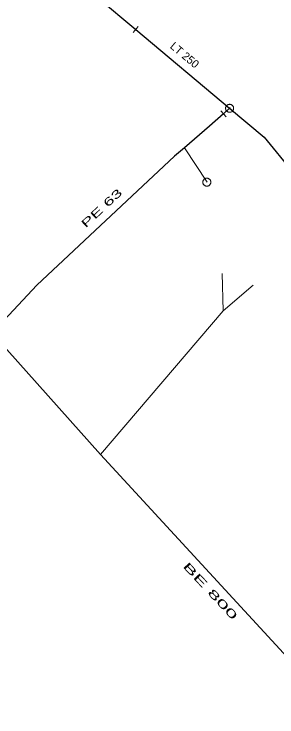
# Model space of a CAD drawing. Extents: x -807203 to -805207, y -993656 to -992505.
# Drawn here: x -805837.6 to -805804.7, y -993521.1 to -993433.3 of the extents above; entities that cross this region are included whole.
import ezdxf

# ---------------------------------------------------------------- set-up
doc = ezdxf.new("R2010")
doc.units = 0
doc.header["$LTSCALE"] = 0.4
for name, color, linetype, lineweight in [('1', 7, 'Continuous', 13), ('11', 7, 'Continuous', 13), ('13', 7, 'Continuous', 13), ('14', 7, 'Continuous', 25), ('17', 7, 'Continuous', 25), ('23', 7, 'Continuous', 13), ('34', 7, 'Continuous', 13), ('47', 7, 'Continuous', 13)]:
    doc.layers.add(name, color=color, linetype=linetype, lineweight=lineweight)

msp = doc.modelspace()

# ---------------------------------------------------------------- linework, layer by layer
at = {"layer": '11'}
msp.add_line((-805811.447, -993470.358), (-805811.581, -993465.673), dxfattribs=at)
msp.add_lwpolyline([(-805807.701, -993467.145), (-805811.447, -993470.358), (-805826.754, -993488.288)], dxfattribs=at)
at = {"layer": '13'}
msp.add_line((-805816.254, -993449.989), (-805813.444, -993454.292), dxfattribs=at)
at = {"layer": '14', "lineweight": 13}
msp.add_line((-805811.384, -993445.766), (-805810.637, -993445.063), dxfattribs=at)
at = {"layer": '14'}
msp.add_lwpolyline([(-805843.754, -993470.162), (-805838.469, -993475.18), (-805826.754, -993488.287), (-805799.036, -993518.404)], dxfattribs=at)
at = {"layer": '17'}
for p, q in [((-805830.275, -993428.564), (-805822.361, -993435.213)), ((-805822.361, -993435.213), (-805810.637, -993445.063))]:
    msp.add_line(p, q, dxfattribs=at)
for points in [[(-805810.637, -993445.063), (-805806.327, -993448.671), (-805795.712, -993461.664), (-805787.671, -993471.416), (-805755.36, -993508.868), (-805722.18, -993547.329), (-805706.16, -993565.899), (-805691.895, -993582.435), (-805667.369, -993617.68)], [(-805811.384, -993445.766), (-805813.146, -993447.293), (-805816.254, -993449.989), (-805817.509, -993451.022), (-805834.715, -993467.127), (-805848.12, -993481.456), (-805848.94, -993482.359), (-805854.633, -993489.281), (-805856.36, -993491.412), (-805860.274, -993496.243), (-805860.927, -993497.096), (-805863.272, -993500.095), (-805876.087, -993516.164)]]:
    msp.add_lwpolyline(points, dxfattribs=at)
at = {"layer": '23'}
for points in [[(-805813.197, -993454.701), (-805813.155, -993454.669), (-805813.116, -993454.633), (-805813.083, -993454.594), (-805813.053, -993454.551), (-805813.027, -993454.506), (-805813.007, -993454.457), (-805812.991, -993454.407), (-805812.981, -993454.357), (-805812.976, -993454.304), (-805812.977, -993454.252), (-805812.982, -993454.2), (-805812.995, -993454.148), (-805813.011, -993454.099), (-805813.033, -993454.052), (-805813.059, -993454.007), (-805813.092, -993453.964), (-805813.126, -993453.927), (-805813.167, -993453.891), (-805813.208, -993453.862), (-805813.253, -993453.835), (-805813.303, -993453.816), (-805813.353, -993453.8), (-805813.405, -993453.79), (-805813.456, -993453.784), (-805813.508, -993453.786), (-805813.561, -993453.792), (-805813.611, -993453.804), (-805813.661, -993453.821), (-805813.708, -993453.843), (-805813.753, -993453.869), (-805813.795, -993453.9), (-805813.834, -993453.936), (-805813.869, -993453.976), (-805813.899, -993454.018), (-805813.923, -993454.063), (-805813.944, -993454.112), (-805813.96, -993454.162), (-805813.97, -993454.214), (-805813.975, -993454.265)], [(-805813.167, -993453.891), (-805813.208, -993453.862), (-805813.253, -993453.835), (-805813.303, -993453.816), (-805813.353, -993453.8), (-805813.405, -993453.79), (-805813.456, -993453.784), (-805813.508, -993453.786), (-805813.561, -993453.792), (-805813.611, -993453.804), (-805813.661, -993453.821), (-805813.708, -993453.843), (-805813.753, -993453.869), (-805813.795, -993453.9), (-805813.834, -993453.936), (-805813.869, -993453.976), (-805813.899, -993454.018), (-805813.923, -993454.063), (-805813.944, -993454.112), (-805813.96, -993454.162), (-805813.97, -993454.214), (-805813.975, -993454.265), (-805813.974, -993454.317), (-805813.968, -993454.37), (-805813.957, -993454.42), (-805813.939, -993454.47), (-805813.917, -993454.517), (-805813.891, -993454.562), (-805813.859, -993454.603), (-805813.824, -993454.642), (-805813.784, -993454.678), (-805813.741, -993454.707), (-805813.696, -993454.733), (-805813.649, -993454.754), (-805813.598, -993454.768), (-805813.547, -993454.779), (-805813.495, -993454.784), (-805813.442, -993454.784), (-805813.39, -993454.777), (-805813.339, -993454.765)], [(-805813.975, -993454.265), (-805813.974, -993454.317), (-805813.968, -993454.37), (-805813.957, -993454.42), (-805813.939, -993454.47), (-805813.917, -993454.517), (-805813.891, -993454.562), (-805813.859, -993454.603), (-805813.824, -993454.642), (-805813.784, -993454.678), (-805813.741, -993454.707), (-805813.696, -993454.733), (-805813.649, -993454.754), (-805813.598, -993454.768), (-805813.547, -993454.779), (-805813.495, -993454.784), (-805813.442, -993454.784), (-805813.39, -993454.777), (-805813.339, -993454.765), (-805813.29, -993454.748), (-805813.243, -993454.726), (-805813.197, -993454.701), (-805813.155, -993454.669), (-805813.116, -993454.633), (-805813.083, -993454.594), (-805813.053, -993454.551), (-805813.027, -993454.506), (-805813.007, -993454.457), (-805812.991, -993454.407), (-805812.981, -993454.357), (-805812.976, -993454.304), (-805812.977, -993454.252), (-805812.982, -993454.2), (-805812.995, -993454.148), (-805813.011, -993454.099), (-805813.033, -993454.052), (-805813.059, -993454.007), (-805813.092, -993453.964), (-805813.126, -993453.927), (-805813.167, -993453.891)], [(-805813.339, -993454.765), (-805813.29, -993454.748), (-805813.243, -993454.726), (-805813.197, -993454.701)]]:
    msp.add_lwpolyline(points, dxfattribs=at)
at = {"layer": '34'}
for p, q in [((-805822.039, -993434.829), (-805822.683, -993435.595)), ((-805811.056, -993446.143), (-805811.711, -993445.387))]:
    msp.add_line(p, q, dxfattribs=at)
at = {"layer": '47'}
for points in [[(-805810.253, -993445.383), (-805810.222, -993445.341), (-805810.194, -993445.296), (-805810.173, -993445.248), (-805810.156, -993445.199), (-805810.144, -993445.148), (-805810.138, -993445.095), (-805810.138, -993445.044), (-805810.142, -993444.992), (-805810.152, -993444.941), (-805810.167, -993444.89), (-805810.188, -993444.842), (-805810.214, -993444.796), (-805810.243, -993444.754), (-805810.278, -993444.714), (-805810.316, -993444.679), (-805810.358, -993444.648), (-805810.403, -993444.62), (-805810.451, -993444.598), (-805810.5, -993444.582), (-805810.551, -993444.57), (-805810.604, -993444.564), (-805810.656, -993444.563), (-805810.708, -993444.568), (-805810.759, -993444.577), (-805810.809, -993444.593), (-805810.857, -993444.614), (-805810.903, -993444.639), (-805810.945, -993444.669), (-805810.985, -993444.704), (-805811.02, -993444.742), (-805811.051, -993444.784), (-805811.079, -993444.829), (-805811.101, -993444.877), (-805811.117, -993444.926), (-805811.129, -993444.977), (-805811.136, -993445.029), (-805811.137, -993445.082), (-805811.132, -993445.134), (-805811.122, -993445.185), (-805811.106, -993445.235), (-805811.085, -993445.283), (-805811.06, -993445.329), (-805811.03, -993445.371), (-805810.995, -993445.411), (-805810.957, -993445.446), (-805810.915, -993445.477), (-805810.87, -993445.505), (-805810.823, -993445.527), (-805810.773, -993445.543), (-805810.722, -993445.555), (-805810.67, -993445.562), (-805810.618, -993445.562), (-805810.566, -993445.557), (-805810.515, -993445.547), (-805810.464, -993445.532), (-805810.416, -993445.511), (-805810.371, -993445.486), (-805810.328, -993445.456), (-805810.288, -993445.421)], [(-805810.574, -993445.115), (-805810.568, -993445.108), (-805810.564, -993445.101), (-805810.561, -993445.093), (-805810.558, -993445.085), (-805810.556, -993445.076), (-805810.555, -993445.068), (-805810.554, -993445.059), (-805810.555, -993445.051), (-805810.557, -993445.043), (-805810.56, -993445.034), (-805810.563, -993445.026), (-805810.567, -993445.019), (-805810.572, -993445.012), (-805810.577, -993445.005), (-805810.584, -993445), (-805810.591, -993444.994), (-805810.598, -993444.99), (-805810.606, -993444.987), (-805810.614, -993444.984), (-805810.623, -993444.982), (-805810.631, -993444.981), (-805810.64, -993444.98), (-805810.648, -993444.981), (-805810.657, -993444.983), (-805810.665, -993444.986), (-805810.673, -993444.989), (-805810.68, -993444.993), (-805810.687, -993444.998), (-805810.694, -993445.003), (-805810.699, -993445.01), (-805810.705, -993445.017), (-805810.709, -993445.024), (-805810.712, -993445.032), (-805810.715, -993445.04), (-805810.717, -993445.049), (-805810.719, -993445.056), (-805810.719, -993445.066), (-805810.718, -993445.074), (-805810.716, -993445.083), (-805810.713, -993445.091), (-805810.71, -993445.099), (-805810.706, -993445.106), (-805810.701, -993445.113), (-805810.696, -993445.12), (-805810.689, -993445.125), (-805810.682, -993445.131), (-805810.675, -993445.135), (-805810.667, -993445.138), (-805810.659, -993445.141), (-805810.65, -993445.143), (-805810.643, -993445.145), (-805810.633, -993445.145), (-805810.625, -993445.144), (-805810.617, -993445.142), (-805810.608, -993445.139), (-805810.6, -993445.136), (-805810.593, -993445.132), (-805810.586, -993445.127), (-805810.579, -993445.122)]]:
    msp.add_lwpolyline(points, close=True, dxfattribs=at)

# ---------------------------------------------------------------- texts
at = {"layer": '1'}
msp.add_text('LT 250', height=1, rotation=320, dxfattribs=at).set_placement((-805818.161, -993437.454))
for s, rotation, width, p in [('PE 63 ', 43, 1.75, (-805828.61, -993460.063)), ('BE 800', 313, 2.1, (-805816.551, -993502.296))]:
    msp.add_text(s, height=1, rotation=rotation, dxfattribs=dict(at, width=width)).set_placement(p)

doc.saveas('drawing.dxf')
